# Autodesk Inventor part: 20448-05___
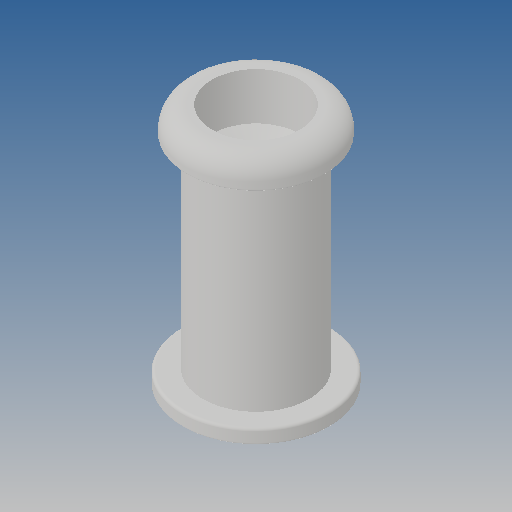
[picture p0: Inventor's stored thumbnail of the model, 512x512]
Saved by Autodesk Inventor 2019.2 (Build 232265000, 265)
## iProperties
Created: 2010-06
Part Number: 20448-05___
Material: Ogólny
Document SubType Name: Modeling
Designer: CADENGINEERING4
Density: 1 g/cm^3
Appearance: Domyślna
Author: CADENGINEERING4
Revision Number: ANY
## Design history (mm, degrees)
feature "NONE"
node "Bryła1"
